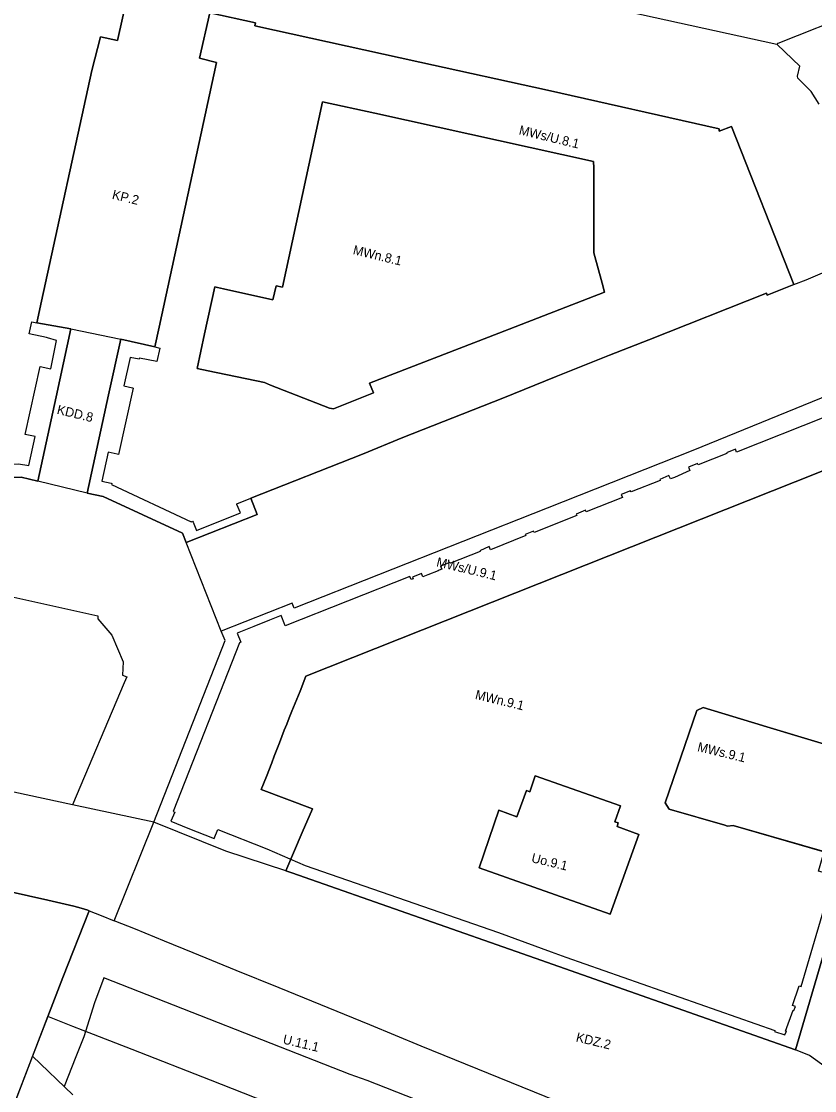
# Model space of a CAD drawing. Extents: x 7429686 to 7432896, y 5547954 to 5550600.
# Drawn here: x 7431092.2 to 7431433.9, y 5548709 to 5549169.6 of the extents above; entities that cross this region are included whole.
import ezdxf

# ---------------------------------------------------------------- set-up
doc = ezdxf.new("R2010")
doc.units = 0
for name, color, linetype in [('granica planu', 7, 'Continuous'), ('linie rozgraniczające', 7, 'Continuous'), ('nieprzekraczalna linia zabudowy', 7, 'Continuous'), ('obowiązująca linia zabudowy', 7, 'Continuous'), ('oznaczenia przeznaczeń', 7, 'Continuous')]:
    doc.layers.add(name, color=color, linetype=linetype)

msp = doc.modelspace()

# ---------------------------------------------------------------- linework, layer by layer
at = {"layer": 'granica planu'}
msp.add_lwpolyline([(7431071.46, 5548657.37), (7431103.57, 5548740.91), (7431110.06, 5548757.75), (7431121.41, 5548786.45), (7431120.87, 5548786.72), (7431118.06, 5548787.64), (7431114.78, 5548788.45), (7431103.64, 5548791.04), (7431087.04, 5548794.84)], dxfattribs=at)
at = {"layer": 'linie rozgraniczające'}
for p, q in [((7431173.39, 5549173.33), (7431168.91, 5549153.67)), ((7431193.1, 5549168.9), (7431173.39, 5549173.33)), ((7431168.91, 5549153.67), (7431176.31, 5549151.9)), ((7431318.87, 5549139.95), (7431263.81, 5549152.05)), ((7431392.81, 5549123.31), (7431318.87, 5549139.95)), ((7431221.91, 5549134.94), (7431204.74, 5549055.11)), ((7431204.74, 5549055.11), (7431221.91, 5549134.94)), ((7431221.91, 5549134.94), (7431244.46, 5549129.99)), ((7431244.46, 5549129.99), (7431338.71, 5549109.29)), ((7431398.12, 5549124.28), (7431392.8, 5549122.25)), ((7431392.8, 5549122.25), (7431392.81, 5549123.31)), ((7431424.93, 5549056.18), (7431398.12, 5549124.28)), ((7431338.72, 5549106.51), (7431338.71, 5549109.29)), ((7431338.71, 5549109.29), (7431338.72, 5549106.51)), ((7431338.79, 5549069.93), (7431338.72, 5549106.51)), ((7431338.72, 5549106.51), (7431338.79, 5549069.93)), ((7431342.36, 5549056.8), (7431338.79, 5549069.93)), ((7431338.79, 5549069.93), (7431342.36, 5549056.8)), ((7431171.15, 5549034.94), (7431175.59, 5549055.18)), ((7431175.59, 5549055.18), (7431176.7, 5549054.93)), ((7431201.98, 5549055.67), (7431204.74, 5549055.11)), ((7431343.39, 5549053.01), (7431342.36, 5549056.8)), ((7431342.36, 5549056.8), (7431343.39, 5549053.01)), ((7431343.39, 5549053.01), (7431297.86, 5549035.32)), ((7431167.91, 5549020.13), (7431171.15, 5549034.94)), ((7431297.86, 5549035.32), (7431242.23, 5549013.7)), ((7431243.93, 5549009.64), (7431242.23, 5549013.7)), ((7431242.23, 5549013.7), (7431243.93, 5549009.64)), ((7431243.93, 5549009.64), (7431226.7, 5549002.75)), ((7431226.7, 5549002.75), (7431224.95, 5549002.96)), ((7431385.82, 5548873.99), (7431411.42, 5548866.34)), ((7431411.42, 5548866.34), (7431411.82, 5548866.07)), ((7431411.82, 5548866.07), (7431464.36, 5548850.33)), ((7431395.15, 5548823.28), (7431371.28, 5548830.24)), ((7431345.8, 5548785.08), (7431358.11, 5548819.38)), ((7431358.11, 5548819.38), (7431345.8, 5548785.08)), ((7431396.28, 5548822.97), (7431395.15, 5548823.28)), ((7431398.8, 5548823.21), (7431396.28, 5548822.97)), ((7431449.93, 5548808.45), (7431398.8, 5548823.21))]:
    msp.add_line(p, q, dxfattribs=at)
for points in [[(7431099.36, 5548971.58), (7431107.22, 5549007.82), (7431113.56, 5549037.12), (7431098.96, 5549039.76), (7431100.87, 5549049.04), (7431122.56, 5549148.42), (7431126.27, 5549162.98), (7431133.65, 5549161.37), (7431137.98, 5549180.79)], [(7431137.98, 5549180.79), (7431133.65, 5549161.37), (7431126.27, 5549162.98)], [(7431417.65, 5549159.61), (7431327.86, 5549179.5)], [(7431418.23, 5549160.27), (7431452.13, 5549173.77)], [(7431135.08, 5549032.7), (7431149.76, 5549029.39), (7431151.58, 5549037.84), (7431176.31, 5549151.9), (7431168.91, 5549153.67), (7431173.39, 5549173.33)], [(7431173.39, 5549173.33), (7431193.1, 5549168.9), (7431192.85, 5549167.65), (7431263.81, 5549152.05), (7431318.87, 5549139.95), (7431392.81, 5549123.31), (7431392.8, 5549122.25), (7431398.12, 5549124.28), (7431424.93, 5549056.18)], [(7431263.81, 5549152.05), (7431192.85, 5549167.65), (7431193.1, 5549168.9)], [(7431126.27, 5549162.98), (7431122.56, 5549148.42), (7431100.87, 5549049.04), (7431098.96, 5549039.76), (7431113.56, 5549037.12)], [(7431417.69, 5549159.57), (7431418.23, 5549160.27)], [(7431417.69, 5549159.57), (7431417.65, 5549159.61)], [(7431427.44, 5549150.24), (7431417.69, 5549159.57)], [(7431176.31, 5549151.9), (7431151.58, 5549037.84), (7431149.76, 5549029.39), (7431135.08, 5549032.7)], [(7431426.47, 5549145.98), (7431427.44, 5549150.24)], [(7431426.63, 5549145.08), (7431426.47, 5549145.98)], [(7431432.34, 5549139.33), (7431426.63, 5549145.08)], [(7431435.89, 5549133.99), (7431432.34, 5549139.33)], [(7431338.71, 5549109.29), (7431244.46, 5549129.99), (7431221.91, 5549134.94)], [(7431430.25, 5549058.28), (7431462.06, 5549071.92)], [(7431424.93, 5549056.18), (7431413.49, 5549051.67), (7431413.12, 5549052.58), (7431362.54, 5549032.39), (7431345.51, 5549025.75), (7431322.63, 5549016.56), (7431299.53, 5549007.29), (7431256.5, 5548990.27), (7431239.22, 5548983.18), (7431191, 5548964.19), (7431193.77, 5548957.21), (7431163.17, 5548945.09)], [(7431175.59, 5549055.18), (7431171.15, 5549034.94), (7431167.91, 5549020.13)], [(7431204.74, 5549055.11), (7431201.98, 5549055.67), (7431200.57, 5549049.65), (7431179.23, 5549054.34), (7431176.7, 5549054.93), (7431175.59, 5549055.18)], [(7431176.7, 5549054.93), (7431179.23, 5549054.34), (7431200.57, 5549049.65), (7431201.98, 5549055.67)], [(7431191, 5548964.19), (7431239.22, 5548983.18), (7431256.5, 5548990.27), (7431299.53, 5549007.29), (7431322.63, 5549016.56), (7431345.51, 5549025.75), (7431362.54, 5549032.39), (7431413.12, 5549052.58), (7431413.49, 5549051.67), (7431424.93, 5549056.18)], [(7431424.93, 5549056.18), (7431430.25, 5549058.28)], [(7431242.23, 5549013.7), (7431297.86, 5549035.32), (7431343.39, 5549053.01)], [(7431113.56, 5549037.12), (7431107.22, 5549007.82), (7431099.36, 5548971.58)], [(7431113.56, 5549037.12), (7431135.08, 5549032.7)], [(7431135.08, 5549032.7), (7431129.82, 5549008.74), (7431120.51, 5548966.39)], [(7431120.51, 5548966.39), (7431129.82, 5549008.74), (7431135.08, 5549032.7)], [(7431167.91, 5549020.13), (7431172.75, 5549019.11), (7431196.94, 5549013.99), (7431199.47, 5549012.89), (7431224.95, 5549002.96)], [(7431224.95, 5549002.96), (7431199.47, 5549012.89), (7431196.94, 5549013.99), (7431172.75, 5549019.11), (7431167.91, 5549020.13)], [(7431458.52, 5549016.21), (7431381.36, 5548984.68)], [(7431224.95, 5549002.96), (7431226.7, 5549002.75), (7431243.93, 5549009.64)], [(7431381.36, 5548984.68), (7431318.67, 5548959.9)], [(7431206.13, 5548803.71), (7431213.17, 5548820.12), (7431217.58, 5548830.4), (7431195.51, 5548838.7), (7431197.77, 5548844.36), (7431200.06, 5548850.23), (7431201.18, 5548853.12), (7431202.3, 5548856.01), (7431203.38, 5548858.81), (7431204.43, 5548861.51), (7431205.48, 5548864.22), (7431206.53, 5548866.91), (7431207.59, 5548869.62), (7431208.67, 5548872.42), (7431212.25, 5548881.05), (7431214.81, 5548887.54), (7431425.44, 5548971.3), (7431442.42, 5548978.05)], [(7431442.42, 5548978.05), (7431425.44, 5548971.3), (7431214.81, 5548887.54)], [(7431099.36, 5548971.58), (7431092.19, 5548973.2), (7431054.42, 5548972.62), (7431050.95, 5548969.47)], [(7431054.42, 5548972.62), (7431092.19, 5548973.2), (7431099.36, 5548971.58)], [(7431120.51, 5548966.39), (7431099.36, 5548971.58)], [(7431120.51, 5548966.39), (7431127.45, 5548964.92), (7431161.66, 5548949.19), (7431163.17, 5548945.09)], [(7431163.17, 5548945.09), (7431161.66, 5548949.19), (7431127.45, 5548964.92), (7431120.51, 5548966.39)], [(7431163.17, 5548945.09), (7431193.77, 5548957.21), (7431191, 5548964.19)], [(7431318.67, 5548959.9), (7431209.74, 5548916.76)], [(7431178.35, 5548906.95), (7431163.17, 5548945.09)], [(7431070.7, 5548925.58), (7431125.23, 5548913.5)], [(7431208.93, 5548918.91), (7431178.35, 5548906.95)], [(7431209.74, 5548916.76), (7431208.93, 5548918.91)], [(7431125.23, 5548913.5), (7431125.16, 5548912.18)], [(7431125.16, 5548912.18), (7431131.15, 5548905.26)], [(7431179.95, 5548902.93), (7431178.35, 5548906.95)], [(7431131.15, 5548905.26), (7431136.04, 5548893.7)], [(7431149.25, 5548824.62), (7431179.95, 5548902.93)], [(7431136.04, 5548893.7), (7431135.73, 5548887.91)], [(7431136.53, 5548884.68), (7431114.24, 5548832.14)], [(7431135.73, 5548887.91), (7431137.65, 5548887.31)], [(7431137.65, 5548887.31), (7431136.53, 5548884.68)], [(7431214.81, 5548887.54), (7431212.25, 5548881.05), (7431208.67, 5548872.42), (7431207.59, 5548869.62), (7431206.53, 5548866.91), (7431205.48, 5548864.22), (7431204.43, 5548861.51), (7431203.38, 5548858.81), (7431202.3, 5548856.01), (7431201.18, 5548853.12), (7431200.06, 5548850.23), (7431197.77, 5548844.36), (7431195.51, 5548838.7), (7431217.58, 5548830.4)], [(7431371.28, 5548830.24), (7431369.44, 5548832.95), (7431383.14, 5548872.81), (7431385.82, 5548873.99)], [(7431411.42, 5548866.34), (7431385.82, 5548873.99), (7431383.14, 5548872.81), (7431369.44, 5548832.95), (7431371.28, 5548830.24), (7431395.15, 5548823.28), (7431396.28, 5548822.97), (7431398.8, 5548823.21), (7431449.93, 5548808.45)], [(7431464.36, 5548850.33), (7431411.82, 5548866.07), (7431411.42, 5548866.34)], [(7431114.24, 5548832.14), (7431045.7, 5548846.88)], [(7431358.11, 5548819.38), (7431348.76, 5548822.71), (7431349.24, 5548824.29), (7431347.89, 5548824.77), (7431350.21, 5548831.73), (7431313.49, 5548844.55), (7431311.25, 5548837.76), (7431309.79, 5548838.22), (7431305.65, 5548826.98), (7431297.86, 5548829.76), (7431289.46, 5548804.98), (7431345.8, 5548785.08)], [(7431345.8, 5548785.08), (7431289.46, 5548804.98), (7431297.86, 5548829.76), (7431305.65, 5548826.98), (7431309.79, 5548838.22), (7431311.25, 5548837.76), (7431313.49, 5548844.55), (7431350.21, 5548831.73), (7431347.89, 5548824.77), (7431349.24, 5548824.29), (7431348.76, 5548822.71), (7431358.11, 5548819.38)], [(7431149.25, 5548824.62), (7431114.24, 5548832.14)], [(7431217.58, 5548830.4), (7431213.17, 5548820.12), (7431206.13, 5548803.71)], [(7431132.25, 5548782.16), (7431149.25, 5548824.62)], [(7431180.31, 5548812.12), (7431149.25, 5548824.62)], [(7431206.13, 5548803.71), (7431180.31, 5548812.12)], [(7431449.93, 5548808.45), (7431448.1, 5548803.02), (7431438.75, 5548771.09), (7431425.69, 5548726.51)], [(7431206.13, 5548803.71), (7431208.72, 5548802.86), (7431313.55, 5548766.01), (7431425.69, 5548726.51)], [(7431425.69, 5548726.51), (7431313.55, 5548766.01), (7431208.72, 5548802.86), (7431206.13, 5548803.71)], [(7431425.69, 5548726.51), (7431438.75, 5548771.09), (7431448.1, 5548803.02)], [(7431087.04, 5548794.84), (7431103.64, 5548791.04), (7431114.78, 5548788.45), (7431118.06, 5548787.64), (7431120.87, 5548786.72), (7431121.41, 5548786.45)], [(7431121.41, 5548786.45), (7431110.06, 5548757.75), (7431103.57, 5548740.91)], [(7431121.41, 5548786.45), (7431126.67, 5548784.47)], [(7431126.67, 5548784.47), (7431132.25, 5548782.16)], [(7431141.4, 5548778.5), (7431132.25, 5548782.16)], [(7431153.86, 5548773.4), (7431141.4, 5548778.5)], [(7431166.25, 5548768.3), (7431153.86, 5548773.4)], [(7431184.76, 5548760.78), (7431166.25, 5548768.3)], [(7431203.32, 5548753.24), (7431184.76, 5548760.78)], [(7431242.32, 5548737.28), (7431203.32, 5548753.24)], [(7431103.57, 5548740.91), (7431096.99, 5548723.79)], [(7431114.4, 5548736.68), (7431103.57, 5548740.91)], [(7431118.87, 5548734.93), (7431114.4, 5548736.68)], [(7431264.49, 5548728.2), (7431242.32, 5548737.28)], [(7431140, 5548726.66), (7431118.87, 5548734.93)], [(7431346.81, 5548694.65), (7431264.49, 5548728.2)], [(7431096.99, 5548723.79), (7431071.46, 5548657.37), (7431073.95, 5548655.85), (7431087.73, 5548647.48), (7431090.74, 5548646.26), (7431120.62, 5548634.28), (7431121.74, 5548633.66), (7431139.89, 5548623.62), (7431141.79, 5548622.57), (7431167.76, 5548605.34), (7431168.74, 5548604.6), (7431185.78, 5548591.8), (7431187.8, 5548590.29), (7431211.94, 5548568.47), (7431213, 5548567.41), (7431226.69, 5548553.76), (7431229.12, 5548551.33), (7431244.4, 5548517.92), (7431276.39, 5548531.74)], [(7431114.38, 5548707.25), (7431096.99, 5548723.79)], [(7431173.64, 5548713.49), (7431140, 5548726.66)], [(7431431.66, 5548724.14), (7431425.69, 5548726.51)], [(7431439.45, 5548718.51), (7431431.66, 5548724.14)], [(7431207.55, 5548700.22), (7431173.64, 5548713.49)]]:
    msp.add_lwpolyline(points, dxfattribs=at)
at = {"layer": 'nieprzekraczalna linia zabudowy'}
msp.add_lwpolyline([(7431127.79, 5548757.61), (7431123.69, 5548746.84), (7431119.11, 5548732.23), (7431115.69, 5548723.52), (7431110.69, 5548710.76)], dxfattribs=at)
at = {"layer": 'obowiązująca linia zabudowy'}
for points in [[(7431035.44, 5548998.87), (7431039.37, 5548994.23), (7431036.15, 5548991.51), (7431049.63, 5548975.58), (7431052.85, 5548978.31), (7431053, 5548978.14), (7431091.06, 5548978.99), (7431095.4, 5548978.21), (7431098.15, 5548990.74), (7431093.85, 5548991.69), (7431100.27, 5549020.87), (7431104.88, 5549019.94), (7431107.42, 5549032.19), (7431103.47, 5549033.22), (7431103.02, 5549033.38), (7431095.59, 5549035), (7431096.75, 5549040.14), (7431098.96, 5549039.76)], [(7431149.76, 5549029.39), (7431151.83, 5549028.85), (7431150.62, 5549023.09), (7431143.09, 5549024.5), (7431142.97, 5549024.06), (7431139.09, 5549024.83), (7431136.42, 5549012.66), (7431140.14, 5549011.7), (7431140.38, 5549011.54), (7431134.06, 5548983), (7431133.55, 5548983.11), (7431129.68, 5548983.96), (7431126.95, 5548971.55), (7431130.92, 5548970.65), (7431131.2, 5548970.59), (7431131.09, 5548970.07), (7431165.33, 5548953.99), (7431166.01, 5548954.23), (7431166.23, 5548953.86), (7431167.7, 5548950.24), (7431186.56, 5548957.85), (7431185.07, 5548961.52), (7431184.97, 5548961.78), (7431191, 5548964.19)], [(7431438.56, 5548999.31), (7431400.27, 5548984.05), (7431399.75, 5548985.37), (7431395.9, 5548983.76), (7431396.05, 5548983.38), (7431383.69, 5548978.53), (7431383.45, 5548979.07), (7431379.52, 5548977.54), (7431380.09, 5548976.07), (7431373.49, 5548973.17), (7431371.82, 5548972.49), (7431371.11, 5548973.9), (7431367.16, 5548972.2), (7431367.31, 5548971.86), (7431354.86, 5548966.94), (7431354.63, 5548967.38), (7431350.52, 5548965.81), (7431351.13, 5548964.54), (7431335.42, 5548958.36), (7431335.19, 5548959.02), (7431331.18, 5548957.35), (7431331.5, 5548956.69), (7431313.13, 5548949.43), (7431312.86, 5548950.06), (7431309.25, 5548948.6), (7431309.56, 5548948.09), (7431294.23, 5548941.94), (7431293.64, 5548943.34)], [(7431293.64, 5548943.34), (7431289.68, 5548941.57), (7431289.83, 5548941.2), (7431277.02, 5548936.14), (7431276.81, 5548936.55), (7431272.81, 5548934.9), (7431273.34, 5548933.63), (7431272.23, 5548933.2), (7431271.69, 5548932.97), (7431267.24, 5548931.12), (7431265.16, 5548930.32), (7431264.52, 5548931.76), (7431260.64, 5548930.19), (7431261.02, 5548929.45), (7431260.09, 5548929.17), (7431259.58, 5548930.42), (7431205.84, 5548909.17), (7431205.65, 5548909.62), (7431204.16, 5548913.61), (7431199.07, 5548911.65), (7431192.38, 5548908.97), (7431185.19, 5548905.99), (7431186.72, 5548902.13), (7431186.24, 5548901.94), (7431157.65, 5548829.24), (7431158.26, 5548829), (7431156.67, 5548825.04), (7431163.88, 5548822.04), (7431175.33, 5548817.56), (7431176.92, 5548821.52), (7431197.91, 5548813.11), (7431214.47, 5548806.04)], [(7431421.06, 5548733.02), (7431421.72, 5548734.55), (7431421.34, 5548734.64), (7431424.56, 5548743.62), (7431424.97, 5548743.51), (7431425.58, 5548745.28), (7431424.32, 5548745.67), (7431427.16, 5548754.1), (7431428.03, 5548753.92), (7431442.08, 5548801.7), (7431435.57, 5548803.59), (7431446.4, 5548840.91), (7431452.94, 5548863.46)], [(7431214.47, 5548806.04), (7431297.68, 5548777.05), (7431320.36, 5548768.8), (7431326.78, 5548766.54), (7431416.67, 5548734.93), (7431416.56, 5548734.52), (7431421.06, 5548733.02)], [(7431344.36, 5548672.89), (7431284.39, 5548696.28), (7431278.85, 5548698.62), (7431269.85, 5548702.18), (7431261.97, 5548705.24), (7431241.16, 5548713.39), (7431233.79, 5548715.99), (7431127.79, 5548757.61)]]:
    msp.add_lwpolyline(points, dxfattribs=at)

# ---------------------------------------------------------------- texts
at = {"layer": 'oznaczenia przeznaczeń'}
for s, rotation, p in [('MWs/U.8.1', 346.4891, (7431306.26, 5549120.97)), ('KP.2', 346.4891, (7431131.04, 5549093.2)), ('MWn.8.1', 346.4891, (7431234.78, 5549069.36)), ('KDD.8', 346.4891, (7431107.28, 5549000.6)), ('MWs/U.9.1', 346.5122, (7431270.73, 5548934.94)), ('MWn.9.1', 346.4891, (7431287.4, 5548877.78)), ('MWs.9.1', 346.4891, (7431383.12, 5548855.31)), ('Uo.9.1', 346.4891, (7431311.63, 5548807.45)), ('U.11.1', 346.4891, (7431204.59, 5548729.34)), ('KDZ.2', 346.5122, (7431330.82, 5548730.25))]:
    msp.add_text(s, height=4, rotation=rotation, dxfattribs=at).set_placement(p)

doc.saveas('drawing.dxf')
